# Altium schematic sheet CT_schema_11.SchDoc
size 281 x 153 mm
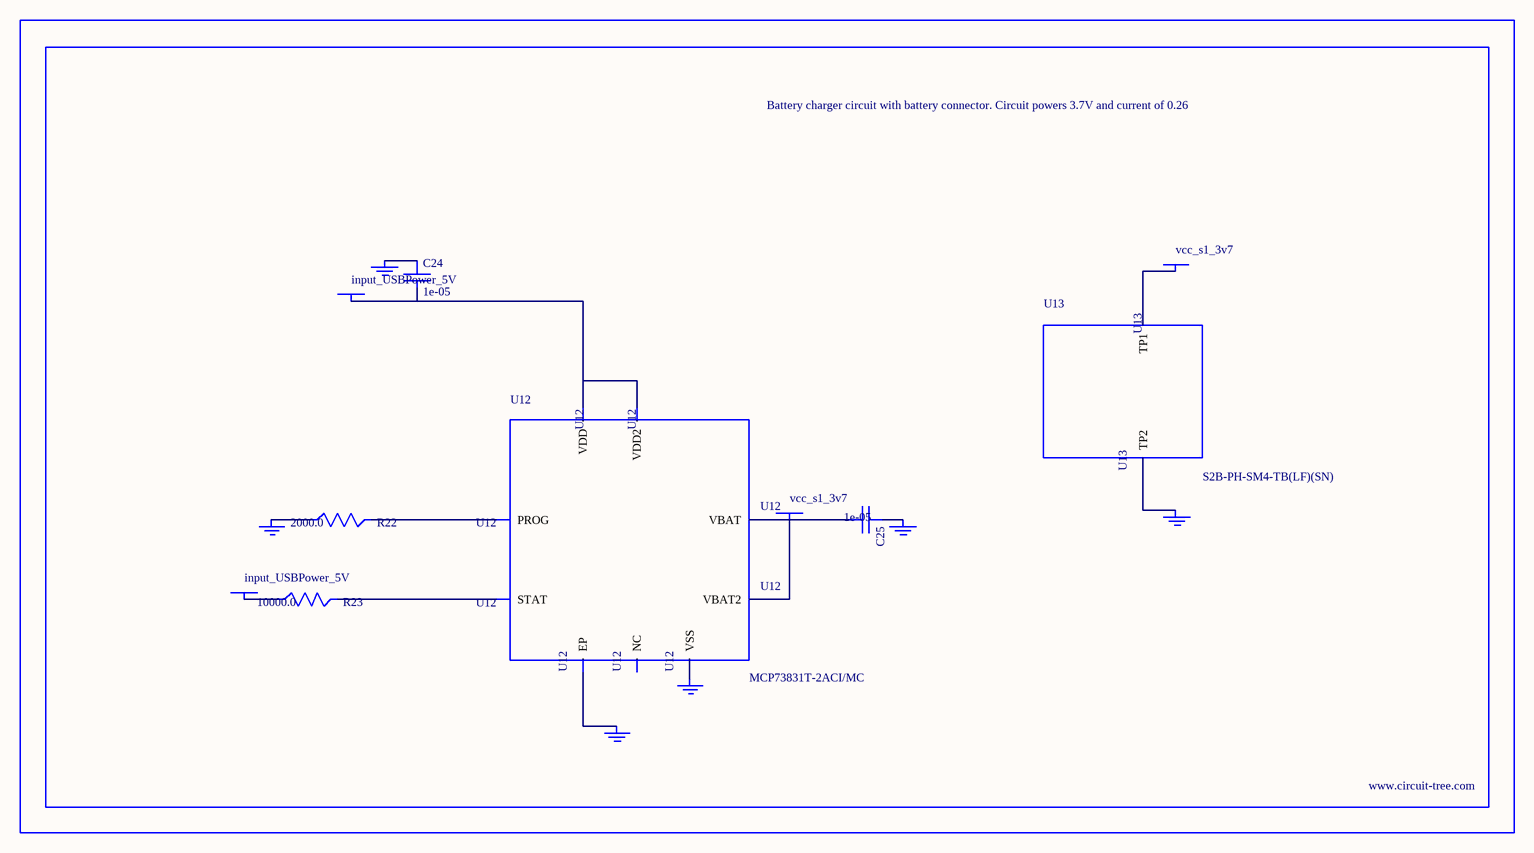
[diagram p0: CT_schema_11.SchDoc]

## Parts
BORDER10  (no value)
C24  1e-05  [C1206]
C25  1e-05  [C1206]
GND_INSTANCE_10_0  (no value)
GND_INSTANCE_10_1  (no value)
GND_INSTANCE_10_2  (no value)
GND_INSTANCE_10_3  (no value)
GND_INSTANCE_10_4  (no value)
GND_INSTANCE_10_5  (no value)
POWER_INSTANCE_10_0  input_USBPower_5V
POWER_INSTANCE_10_1  input_USBPower_5V
POWER_INSTANCE_10_2  vcc_s1_3v7
POWER_INSTANCE_10_3  vcc_s1_3v7
R22  2000.0  [R0603]
R23  10000.0  [R0603]
U12  MCP73831T-2ACI/MC  [DFN8_2X3MC]
U13  S2B-PH-SM4-TB(LF)(SN)  [JST-2-SMD]

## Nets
NetC24_1: C24.1 GND_INSTANCE_10_0.0(GND)
NetC24_2: C24.2 POWER_INSTANCE_10_0.0(PWR) U12.1(VDD) U12.2(VDD2)
NetC25_1: C25.1 GND_INSTANCE_10_1.0(GND)
NetC25_2: C25.2 POWER_INSTANCE_10_2.0(PWR) U12.3(VBAT) U12.4(VBAT2)
NetGND_INSTANCE_10_2_0: GND_INSTANCE_10_2.0(GND) R22.1
NetGND_INSTANCE_10_3_0: GND_INSTANCE_10_3.0(GND) U12.9(EP)
NetGND_INSTANCE_10_4_0: GND_INSTANCE_10_4.0(GND) U12.6(VSS)
NetGND_INSTANCE_10_5_0: GND_INSTANCE_10_5.0(GND) U13.2(TP2)
NetPOWER_INSTANCE_10_1_0: POWER_INSTANCE_10_1.0(PWR) R23.1
NetPOWER_INSTANCE_10_3_0: POWER_INSTANCE_10_3.0(PWR) U13.1(TP1)
NetR22_2: R22.2 U12.8(PROG)
NetR23_2: R23.2 U12.5(STAT)

Not connected (* = marked no-connect by the designer): U12 7(NC)

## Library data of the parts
BORDER10 = BORDER_PAGE10
C24 C25 = C1206C106K3RACTU
GND_INSTANCE_10_0-GND_INSTANCE_10_5 = GND
POWER_INSTANCE_10_0-POWER_INSTANCE_10_3 = PWR
R22 = RC0603JR-072KL
R23 = RC0603JR-0710KL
